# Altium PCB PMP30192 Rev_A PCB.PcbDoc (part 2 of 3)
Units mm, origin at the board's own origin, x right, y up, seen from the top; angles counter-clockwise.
Board outline 142.24 x 157.48 mm, 4 copper layers (Top Layer, Signal Layer 1, Signal Layer 2, Bottom Layer), stack 1.647 mm thick; 198 components, 99 nets, 479 pads, 192 vias.
Unrouted connection lines stored in the file: 2.
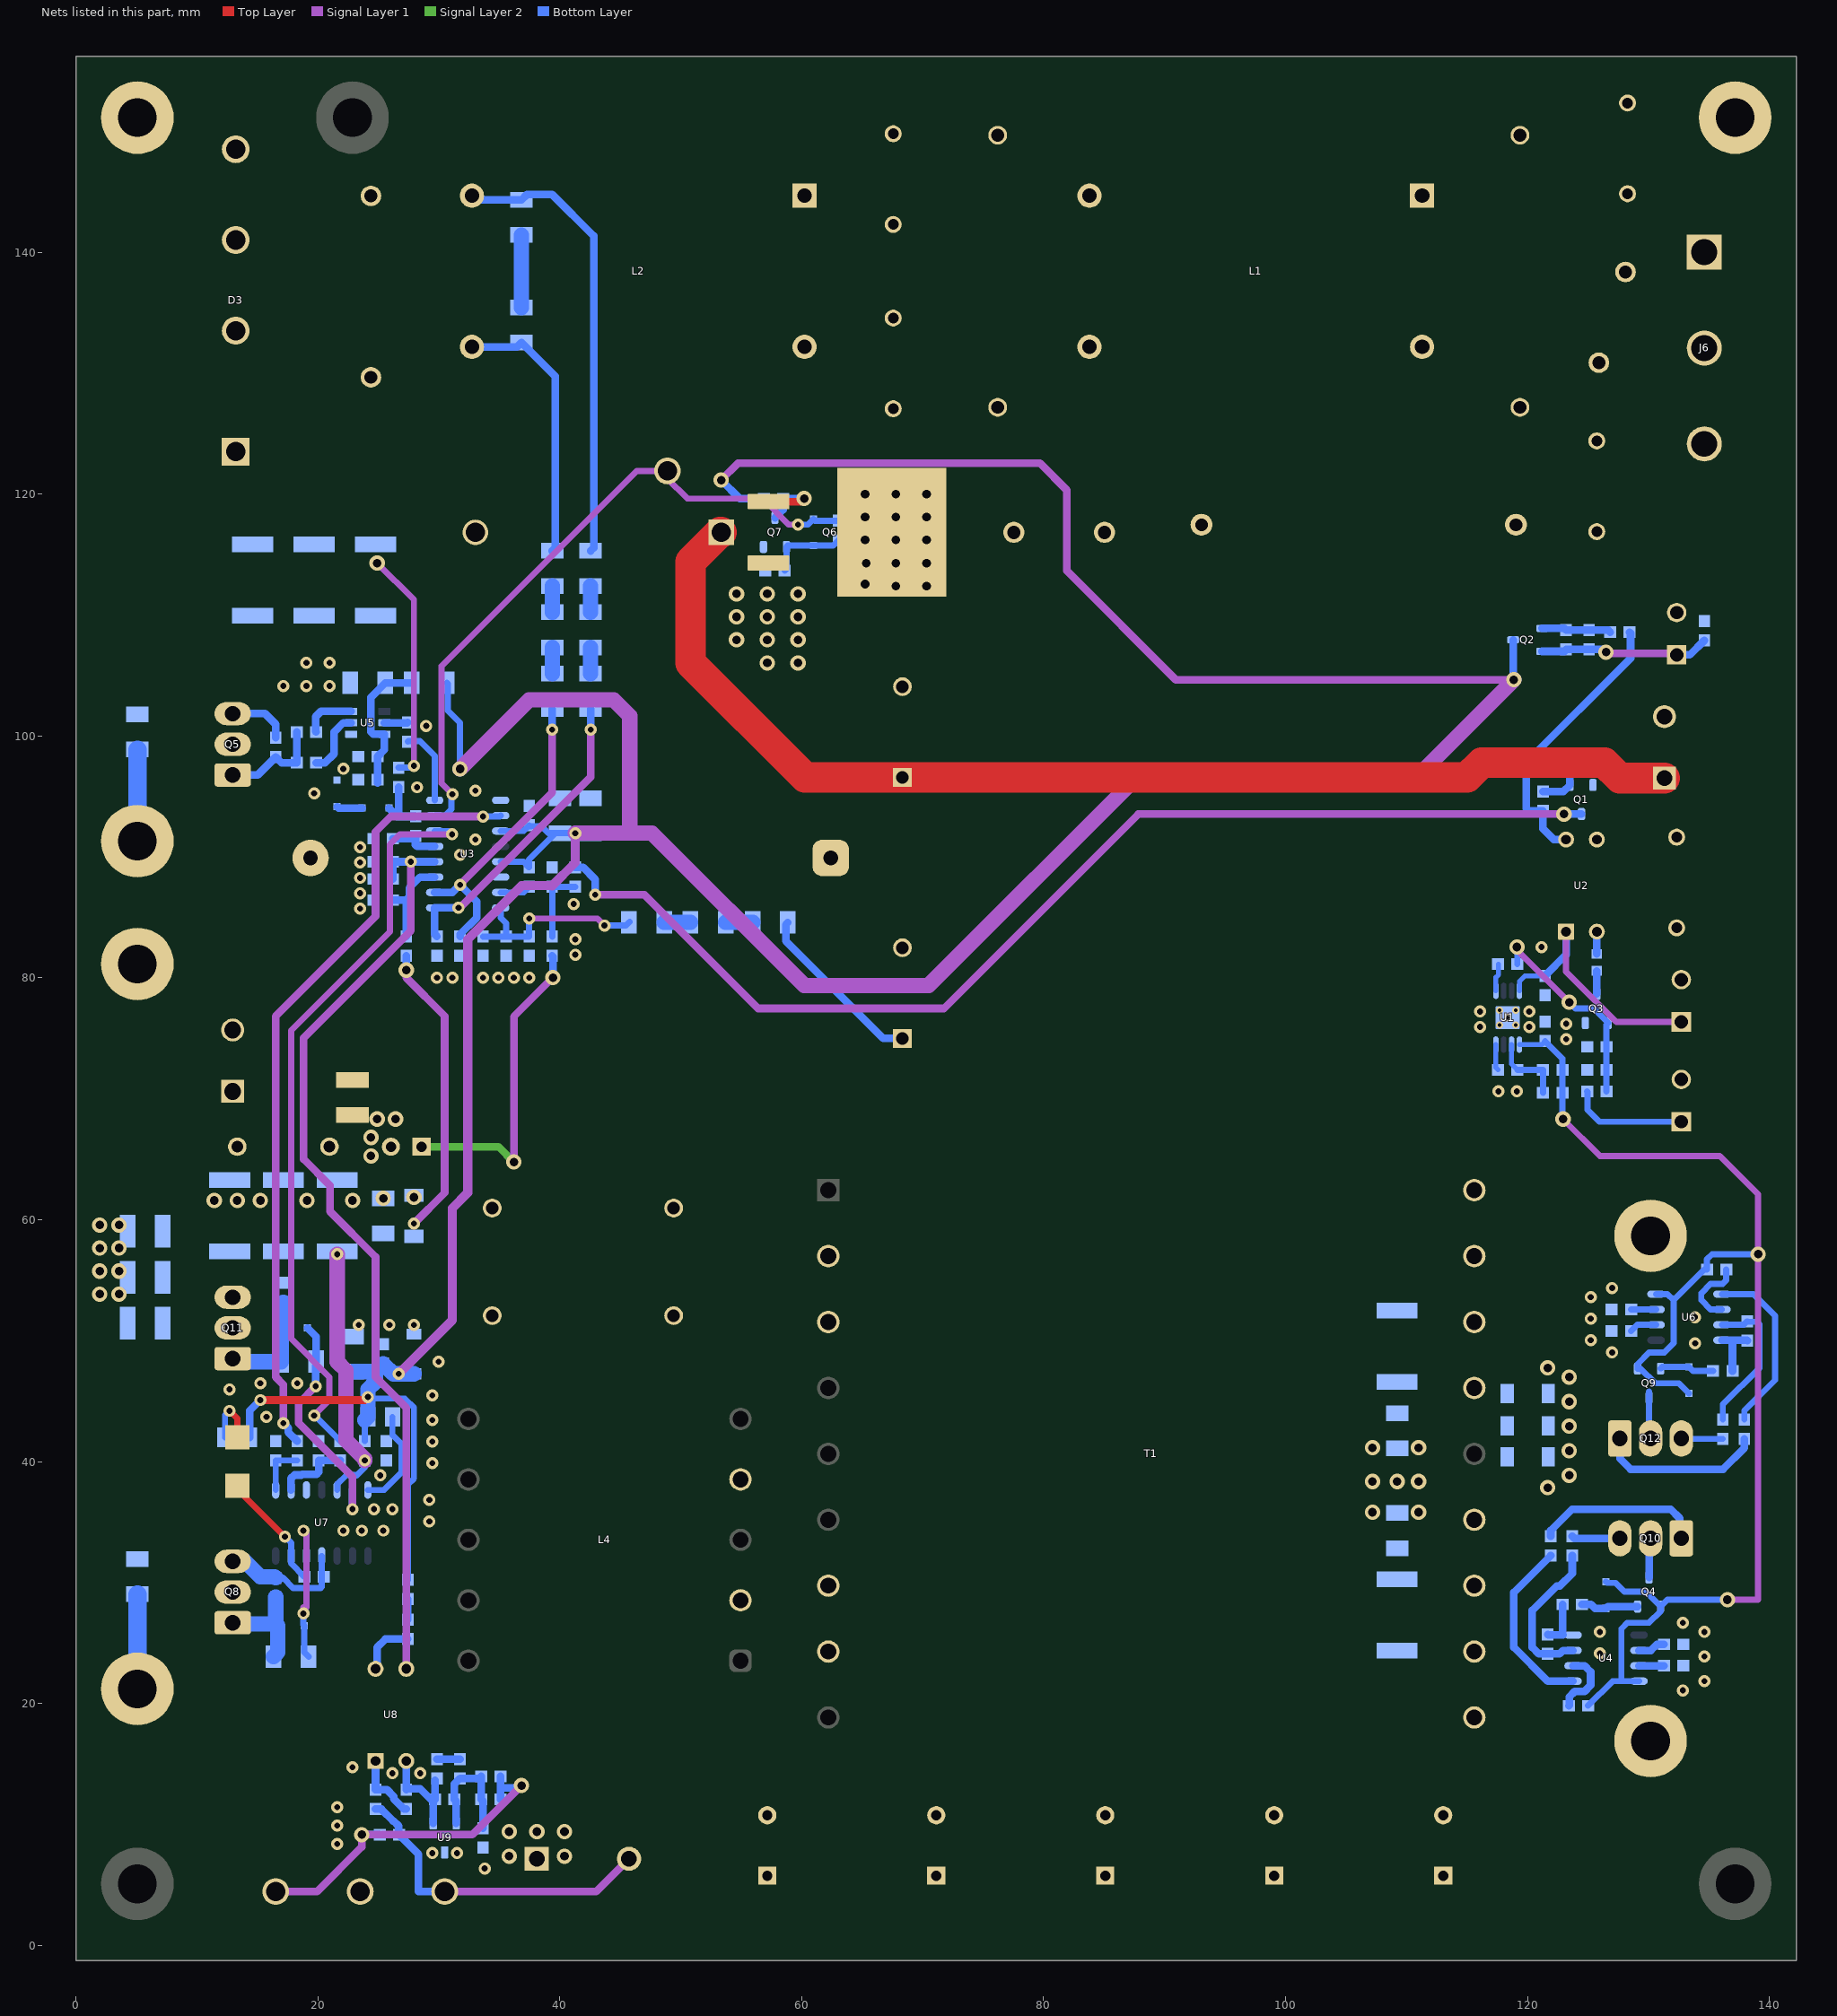
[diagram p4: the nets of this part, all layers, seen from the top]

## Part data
C1: "CAP, CERM, 4.7 µF, 10 V, +/- 20%, X5R, 0603"
C2 C27 C40 C41 C45: "CAP, CERM, 1 µF, 50 V, +/- 10%, X7R, 0603"
C3 C5 C8: "CAP, CERM, 0.01 µF, 100 V, +/- 5%, X7R, 0603"
C4 C6 C7 C16 C33 C43 C60: "CAP, CERM, 0.1uF, 50V, +/-10%, X7R, 0603"
C9 C10 C32 C59: "CAP, CERM, 10uF, 35V, +/-10%, X7R, 1206"
C11 C62: "CAP, CERM, 100 pF, 25 V, +/- 10%, X7R, 0603"
C12 C13 C14: "CAP, CERM, 470pF, 50V, +/-10%, X7R, 0603"
C15: "CAP, CERM, 1000pF, 50V, +/-10%, X7R, 0603"
C17 C63: "CAP, CERM, 2200 pF, 50 V, +/- 10%, X7R, 0603"
C18 C23: library part DE6B3KJ221KN3A, "CAP CER 100PF 300VAC 10% RADIAL"
C19 C26: "CAP, CERM, 220 pF, 300 V, +/- 10%, B, TH, 2- Leads, Body 8x7mm, Pin Spacing 7.5mm"
C20 C38: "CAP, CERM, 1 µF, 10 V, +/- 10%, X5R, 0603"
C21 C22: "CAP, Film, 0.47uF, 275V, +/-20%, TH"
C24: "CAP, Film, 0.33uF, 275V, +/-20%, TH"
C25 C39: "CAP, CERM, 47 pF, 50 V, +/- 5%, C0G/NP0, 0603"
C28 C29: library part 400KXW220MEFC18X45, "CAP, AL, 150 µF, 450 V, +/- 20%, TH"
C30 C31 C34: "CAP, CERM, 10 µF, 50 V, +/- 10%, X5R, 1206"
C35: "CAP, CERM, 2200 pF, 300 V, +/- 20%, E, TH, 2- Leads, Body 9x7mm, Pin Spacing 7.5mm"
C42 C58: library part Capacitor, "CAP, CERM, xxxF, xxV, [TempCo], xx%, [PackageReference]"
C44a C44b C44c C65: "CAP, CERM, 0.047 µF, 630 V, +/- 10%, X7R, 1210"
C46 C47 C48 C49 C50: library part 63ZLH470M12.5X25, "CAP, AL, 470 µF, 50 V, +/- 20%, 0.027 ohm, TH"
C52 C54: "CAP, CERM, 100pF, 50V, +/-1%, C0G/NP0, 0603"
C53: library part 121MPE223J, "CAP, Film, 0.018 µF, 1250 V, +/- 5%, TH"
C55: library part 121MPE223J, "CAP, Film, 0.015 µF, 1250 V, +/- 5%, TH"
C56: "CAP, CERM, 22 µF, 10 V, +/- 20%, X6S, 1206"
C57: "CAP, CERM, 47 µF, 16 V, +/- 15%, X5R, 1206"
C61: "CAP, CERM, 220 pF, 50 V, +/- 5%, C0G/NP0, 0603"
C64 C67: "CAP, CERM, 1000 pF, 630 V, +/- 10%, X7R, 1206"
D1 D2: "Diode, Ultrafast, 100V, 0.25A, SOD-323"
D3: library part GBJ3502-BP, "Diode, P-N-Bridge, 600 V, 15 A, TH"
D4: "Diode, Switching-Bridge, 600V, 3A, TH"
D5 D7 D8: "Diode, Ultrafast, 100 V, 0.25 A, SOD-323"
D6: "Diode, Schottky, 600V, 4A, TH"
D9 D11: library part BAS316,115, "Diode, Ultrafast, 100V, 0.25A, SOD-323"
D10: "Diode, Ultrafast, 600 V, 1 A, SMA"
D12: "Diode, Zener, 18V, 500mW, SOD-123"
F1: "Fuse, 8A, 250V, TH"
Fx1 Fx2 Fx3 TP2: library part PAD_100mil-40milhole, "100mil pad, 40mil hole"
HS1-Pin1 HS1-Pin2 HS3-Pin1 HS3-Pin2 HS4-ML26AAG-1 HS4-ML26AAG-2 TP7: "Test Point, Multipurpose, White, TH"
J1: "Terminal Block, 5.08 mm, 2x1, TH"
J2 J3 J5: "Terminal Block, 3.5 mm, 2x1, Tin, TH"
J4: "Header, 100mil, 2x1, TH"
J6: "Header, 312mil, 3x1, Tin, TH"
J7: "Jumper Wire, 300mil spacing, Orange, pkg of 200"
J8: "Terminal Block, 2x1, 7.62mm, TH"
L1: library part 744834405, "Coupled inductor, 1 mH, 10 A, 12.5mohm, TH"
L2: library part 744834405, "Coupled inductor, 3.3 mH, 5 A, 2 x 37mOhm, TH"
L3: "Inductor, Toroid, 470 µH, 0.11 ohm, TH"
L4: "Inductor, 54 µH, 0.0372 ohm, TH"
Q1 Q3: "MOSFET, N-CH, 60 V, 0.17 A, SOT-23"
Q2: library part "MMBT4403, Fairchild Semiconductor", "Transistor, PNP, 40 V, 0.6 A, SOT-23"
Q4 Q9: "MOSFET, N-CH, 100 V, 0.17 A, SOT-23"
Q5 Q8 Q11: library part IPP60R199CP, "MOSFET, N-CH, 600 V, 45 A, TO-220AB"
Q6: library part STB23NM50N, "MOSFET N CH 650V 35A D2PAK"
Q7: "MOSFET, N-CH, 50 V, 0.22 A, SOT-23"
Q10 Q12: library part "IPP023NE7N3 G", "MOSFET, N-CH, 100 V, 69 A, TO-220AB"
R1: "RES, 100, 1%, 0.1 W, 0603"
R2 R6 R21 R42: "RES, 100 k, 1%, 0.1 W, 0603"
R3 R10 R11 R15: "RES, 10.0 k, 1%, 0.1 W, 0603"
R4: "RES, 768 k, 1%, 0.1 W, 0603"
R5: "RES, 237 k, 1%, 0.1 W, 0603"
R7 R8 R9 R12 R13 R14: "RES, 3.09Meg ohm, 1%, 0.25W, 1206"
R16: "RES, 1.00 k, 1%, 0.1 W, 0603"
R17 R18 R19: "RES, 10.0Meg ohm, 1%, 0.25W, 1206"
R20: "RES, 1.0 k, 5%, 0.1 W, 0603"
R22: "RES, 75.0k ohm, 1%, 0.1W, 0603"
R23: "RES, 3.3Meg ohm, 5%, 0.1W, 0603"
R24 R25: "RES, 470 ohm, 1%, 0.1W, 0603"
R26: "RES, 2.21 k, 1%, 0.1 W, 0603"
R27: "RES, 3.32k ohm, 1%, 0.1W, 0603"
R28 R31: "RES, 475 k, 1%, 0.25 W, 1206"
R29: "RES, 3.3, 5%, 0.1 W, 0603"
R30 R36 R44 R49: "RES, 10.0, 1%, 0.1 W, 0603"
R32 R45: "RES, 100k ohm, 1%, 0.1W, 0603"
R33 R46: "RES, 221k ohm, 1%, 0.1W, 0603"
R34: "RES, 10, 5%, 0.1 W, 0603"
R35: "RES, 1.00, 1%, 0.1 W, 0603"
R37: "RES, 0, 5%, 0.25 W, 1206"
R38 R50 R58 R67 R70: "RES, 10.0k ohm, 1%, 0.1W, 0603"
R39 R40 R41: "RES, 0.08, 1%, 3 W, 2512"
R43: "RES, 221 k, 1%, 0.1 W, 0603"
R47 R56: "RES, 3.30 ohm, 1%, 0.25W, 1206"
R48: "RES, 2.2, 5%, 0.125 W, 0805"
R51: "RES, 1.00 ohm, 1%, 0.125W, 0805"
R52 R62: "DNP"
R53 R55: "RES, 51.1, 1%, 0.1 W, 0603"
R54 R57 R65: "RES, 0, 5%, 0.1 W, 0603"
R59 R60 R61: "RES, 1.00, 1%, 1 W, 2512"
R63: "RES, 20.0 k, 1%, 0.1 W, 0603"
R64: "RES, 49.9, 1%, 0.1 W, 0603"
R66: "RES, 1.21 k, 1%, 0.1 W, 0603"
R68: "RES, 107 k, 1%, 0.1 W, 0603"
R69: "RES, 19.6 k, 1%, 0.1 W, 0603"
RT1: library part B57237S229M, "Thermistor NTC, 22 ohm, 20%, 15x7mm"
RV1: "Varistor, 430V, 4.5KA, TH"
T1: "Transformer, 280 uH, TH"
TP1 TP5: "Test Point, Multipurpose, Red, TH"
TP6: "Test Point, Multipurpose, Black, TH"
U1: "Single Output LDO, 50 mA, Adjustable 1.175 to 26 V Output, 7 to 28 V Input, 8-pin MSOP (DGN), -40 to 125 degC, Green (RoHS & no Sb/Br)"
U2 U8: library part LTV-817, "Opto-Isolator, 1 Channel, TH"
U3: "CCM PFC and LLC Combo Controller, D0016A"
U4 U6: "GREEN Rectifier Controller Device, D0008A"
U5: "2.5-A and 5-A, 35-VMAX VDD FET and IGBT Single-Gate Driver, DBV0006A"
U7: "High-Speed,4A, 600V High-side Low-side Gate Driver Device, D0014A (SOIC-14)"
U9: "Adjustable Precision Shunt Regulator, 34 ppm / degC, 100 mA, -40 to 85 degC, 3-pin SOT-23 (DBZ), Green (RoHS & no Sb/Br)"

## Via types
v1: diameter 1, hole 0.5, Top Layer to Bottom Layer, 106 vias
v2: diameter 1.27, hole 0.711, Top Layer to Bottom Layer, 81 vias
v3: diameter 0.6, hole 0.3, Top Layer to Bottom Layer, 5 vias

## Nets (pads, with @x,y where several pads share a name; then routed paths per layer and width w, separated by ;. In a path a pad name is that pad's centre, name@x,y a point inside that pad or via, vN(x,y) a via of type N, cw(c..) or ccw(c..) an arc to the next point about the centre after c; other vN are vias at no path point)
5VS: C1.1 C5.2 C20.1 C38.1 D5.1 D7.1 Q4.1 Q9.1 R4.2 U1.1 U4.4 U6.4 | length 112.2
  Signal Layer 1 w0.508: v2(122.936,68.326) 125.984,65.278 135.89,65.278 139.065,62.103 v2(139.065,57.15) 139.065,28.575 v2(136.525,28.575)
  Bottom Layer w0.406: U1.1@119.331,74.483 121.168,74.483 C1.1@121.45,74.765
  Bottom Layer w0.508: C1.1@121.45,74.765 122.885,73.33 R4.2@122.885,72.39 C5.2@122.885,70.485 122.885,68.377 v2(122.936,68.326) ; C20.1@125.006,19.812 127.038,21.844 127.762,21.844 ; D5.1@126.492,30.056 126.576,29.972 127.267,29.972 128.004,29.235 129.773,29.235 Q4.1@130.998,28.01 ; U4.4@129.217,21.844 127.762,21.844 ; U6.4@130.625,53.848 131.572,53.848 132.08,53.34 ; D7.1@133.35,45.636 132.504,46.482 130.548,46.482 129.348,47.682 Q9.1@129.098,47.682 129.098,48.072 130.048,49.022 131.318,49.022 132.08,49.784 132.08,53.34 ; v2(136.525,28.575) 131.563,28.575 Q4.1@130.998,28.01 ; v2(139.065,57.15) 135.255,57.15 134.836,56.731 C38.1@134.836,55.88 134.62,55.88 132.08,53.34 ; 127.762,21.844 127.762,26.162 128.27,26.67 130.048,26.67 130.998,27.62 Q4.1@130.998,28.01
5VS_ENA: R11.1 U1.5 | length 2.3
  Bottom Layer w0.406: U1.5@117.381,78.933 117.381,80.043 117.602,80.264 R11.1@117.602,81.107
7VS: C4.1 J2.1 U1.8 U2.1 | length 22
  Signal Layer 1 w0.508: U2.1@123.19,83.82 123.19,80.518 127.353,76.355 J2.1@132.715,76.355
  Bottom Layer w0.406: U1.8@119.331,78.933 119.331,79.707 119.799,80.175 C4.1@121.45,80.175
  Bottom Layer w0.635: C4.1@121.45,80.175 123.19,81.915 U2.1@123.19,83.82
12V: C7.1 C9.2 C10.2 C41.2 C59.2 C60.1 D12.1 Q2.3 R6.1 R37.1 R42.2 R48.1 R51.2 R65.1 U3.3 U3.5 | length 321.9
  Top Layer w0.635: v1(15.24,45.085) 23.876,45.085 v1(24.13,45.339)
  Signal Layer 1 w0.635: v2(53.34,121.158) 54.737,122.555 79.7,122.555 81.915,120.34 81.915,113.665 90.932,104.648 v2(118.872,104.648)
  Signal Layer 1 w0.762: v1(26.67,47.258) 31.115,51.703 31.115,60.96 32.385,62.23 32.385,83.185 36.83,87.63 39.36,87.63 39.37,87.62 41.275,89.525 v1(41.275,91.962)
  Signal Layer 1 w1.27: v2(31.75,97.282) 37.465,102.997 44.45,102.997 45.783,101.663 45.783,92.026 45.72,91.962 ; v1(41.275,91.962) 45.72,91.962 ; v2(118.872,104.648) 111.379,97.155 88.265,97.155 70.485,79.375 60.212,79.375 47.625,91.962 45.72,91.962
  Bottom Layer w0.508: C41.2@23.876,41.694 R51.2@23.876,43.434 ; 24.13,44.704 24.638,45.212 27.178,45.212 27.94,44.45 27.94,38.608 27.432,38.1 R65.1@27.432,30.222 ; R37.1@30.66,104.394 30.734,104.32 30.734,102.108 31.75,101.092 v2(31.75,97.282) ; U3.5@35.11,89.602 36.995,89.602 R6.1@37.465,89.132 37.465,89.79 C9.2@39.638,91.962 ; U3.3@35.11,92.142 36.995,92.142 C7.1@37.465,92.612 37.554,92.523 38.481,92.523 39.042,91.962 C9.2@39.638,91.962 ; C10.2@42.545,91.962 v1(41.275,91.962) C9.2@40.005,91.962 C9.2@39.638,91.962
  Bottom Layer w0.635: R48.1@14.351,42.005 14.351,44.196 v1(15.24,45.085) ; v2(53.34,121.158) 54.864,119.634 R42.2@56.858,119.634 ; Q2.3@118.815,107.95 118.815,104.705 v2(118.872,104.648)
  Bottom Layer w1.27: C59.2@22.86,47.445 24.75,47.445 ; R51.2@23.876,43.434 R51.2@24.13,43.688 24.13,44.704 v1(24.13,45.339) 24.13,45.974 24.75,46.594 24.75,47.445 ; D12.1@27.94,47.258 v1(26.67,47.258) 26.237,47.258 C60.1@25.4,48.095 24.75,47.445
29V: C30.1 C31.1 C34.1 C46.1 C47.1 C48.1 C49.1 C50.1 J8.2 R63.2 R64.2 T1.12 T1.13 T1.15 T1.16 TP5.1 | length 27.1
  Signal Layer 1 w0.635: TP5.1@30.48,4.445 43.01,4.445 J8.2@45.72,7.155
  Bottom Layer w0.635: R63.2@24.765,11.265 25.273,11.265 25.273,11.226 26.212,10.287 26.252,10.287 26.67,9.869 26.67,9.182 R64.2@26.708,9.144 28.321,7.531 28.321,4.445 TP5.1@30.48,4.445
AC1: D3.2 L2.3 R12.2 R28.2 | length 23.1
  Bottom Layer w0.635: L2.3@33.02,131.892 L2.3@32.732,132.18 36.475,132.18 R28.2@36.83,132.535 39.624,129.741 39.624,115.563 R12.2@39.37,115.309
AC2: D3.3 L2.2 R7.2 R31.1 | length 38
  Bottom Layer w0.635: L2.2@32.732,144.68 33.087,144.325 R31.1@36.83,144.325 37.285,144.78 39.37,144.78 42.799,141.351 42.799,115.563 R7.2@42.545,115.309
AC_DET: D8.1 R43.1 TP1.1 U3.15 | length 55.8
  Signal Layer 1 w0.508: v1(31.115,95.187) 30.226,96.076 30.226,105.791 46.355,121.92 TP1.1@48.895,121.92 48.895,121.285 50.546,119.634 56.783,119.634 58.942,117.475 v1(59.69,117.475)
  Bottom Layer w0.508: U3.15@29.66,93.412 30.53,93.412 31.048,93.93 31.048,95.12 v1(31.115,95.187) ; v1(59.69,117.475) 60.495,117.475 D8.1@60.96,117.94 61.103,117.797 R43.1@63.05,117.797
BULK: C28.1 C29.1 C65.2 D4.1 D6.1 J1.1 J7.2 R17.1 | length 112
  Top Layer w2.54: D4.1@53.34,116.84 53.249,116.84 50.8,114.391 50.8,106.045 60.265,96.58 C28.1@68.326,96.58 114.995,96.58 116.205,97.79 126.365,97.79 127.635,96.52 J1.1@131.318,96.52
  Bottom Layer w0.635: R17.1@58.854,84.582 58.674,84.402 58.674,83.058 66.742,74.99 C29.1@68.326,74.99
FB: C17.1 R27.1 U3.12 U8.3 | length 78.8
  Signal Layer 1 w0.635: U8.3@27.305,22.86 27.305,44.45 24.765,46.99 24.765,56.92 20.993,60.691 20.993,62.827 18.82,65 18.82,75.044 27.686,83.91 v1(27.686,89.602)
  Bottom Layer w0.635: R27.1@26.2,88.172 C17.1@26.2,89.602 v1(27.686,89.602) U3.12@29.66,89.602
GD1: R55.2 U3.14 | length 62.5
  Signal Layer 1 w0.508: v1(19.685,43.815) 20.955,45.085 20.955,46.99 17.78,50.165 17.78,75.651 25.949,83.82 25.949,91.033 26.782,91.865 v1(31.098,91.865)
  Bottom Layer w0.508: v1(19.685,43.815) 19.723,43.815 R55.2@21.844,41.694 ; U3.14@29.66,92.142 30.82,92.142 v1(31.098,91.865)
GD2: R53.2 U3.2 | length 65.4
  Signal Layer 1 w0.508: 25.999,93.309 26.035,93.345
  Signal Layer 1 w0.635: v1(17.145,43.18) 17.145,46.355 16.51,46.99 16.51,76.835 24.765,85.09 24.765,92.075 25.999,93.309 ; 26.035,93.345 v1(33.655,93.345)
  Bottom Layer w0.508: v1(33.655,93.345) 35.043,93.345 U3.2@35.11,93.412
  Bottom Layer w0.635: v1(17.145,43.18) 17.145,43.177 17.557,42.766 17.557,42.425 R53.2@18.288,41.694
GND: C18.2 C19.2 C23.1 C26.1 J6.2 TP2.1
HIGH_POWER: J5.1 R20.1 | length 9.7
  Bottom Layer w0.508: R20.1@124.93,70.612 124.968,70.574 124.968,69.088 125.956,68.1 J5.1@132.715,68.1
LLC_RCS: C41.1 C44a.1 C44b.1 C44c.1 C53.2 C55.2 C56.1 C57.1 Q11.3 R26.1 R58.2 R59.2 R60.2 R61.2 U7.5 | length 46.5
  Signal Layer 1 w0.635: v2(27.305,80.645) 27.305,80.01 30.48,76.835 30.48,62.23 v1(27.94,59.69)
  Signal Layer 1 w1.27: v1(21.59,57.15) 21.59,48.26 22.319,47.531 22.319,41.769 23.876,40.212 v1(23.876,40.094)
  Bottom Layer w0.508: U7.5@21.59,37.65 21.59,38.1 22.373,38.883 23.195,38.883 23.216,38.862 23.876,39.522 v1(23.876,40.094) C41.1@23.838,40.056
  Bottom Layer w0.635: v2(27.305,80.645) R26.1@27.305,81.817
LP_ON: R3.1 R15.1 U2.4 | length 23.4
  Bottom Layer w0.635: U2.4@123.19,91.44 122.174,91.44 121.285,92.329 R3.1@121.285,93.815 120.053,93.815 119.888,93.98 119.888,97.79 128.524,106.426 128.524,108.496 R15.1@128.435,108.585
MD_SEL: C2.2 R1.2 R2.2 R6.2 U3.7 | length 10.5
  Bottom Layer w0.508: U3.7@35.11,87.062 36.995,87.062 R6.2@37.465,87.532 C2.2@39.37,87.532 ; R2.2@39.37,83.417 C2.2@39.37,87.532 ; R1.2@41.275,87.532 C2.2@39.37,87.532
NetC3_2: C3.2 Q1.1 R3.2 | length 4.5
  Bottom Layer w0.635: R3.2@121.285,95.415 122.975,95.415 Q1.1@123.51,95.95 123.51,97.775 C3.2@123.66,97.925
NetC5_1: C5.1 R4.1 R5.2 U1.2 | length 6.3
  Bottom Layer w0.406: U1.2@118.681,74.483 118.681,72.873 R5.2@119.164,72.39
  Bottom Layer w0.508: R5.2@119.164,72.39 R4.1@121.285,72.39 C5.1@121.285,70.485
NetC6_1: C6.1 C8.1 J3.1 Q2.2 R10.1 | length 14.2
  Signal Layer 1 w0.635: v2(126.492,106.934) 126.591,106.835 J3.1@132.395,106.835
  Bottom Layer w0.635: Q2.2@121.215,107 123.04,107 C8.1@123.19,107.15 R10.1@125.095,107.15 126.276,107.15 v2(126.492,106.934) ; J3.1@132.334,106.708 133.416,106.708 C6.1@134.62,107.912
NetC8_2: C8.2 Q2.1 R10.2 R15.2 | length 5.8
  Bottom Layer w0.635: Q2.1@121.215,108.9 123.04,108.9 C8.2@123.19,108.75 R10.2@125.095,108.75 126.67,108.75 R15.2@126.835,108.585
NetC11_1: C11.1 Q3.1 R11.2 R20.2 R21.2 | length 17.4
  Signal Layer 1 w0.508: v2(119.126,82.55) 119.126,82.296 v2(123.444,77.978)
  Bottom Layer w0.508: R11.2@119.156,81.153 v2@119.156,82.52 ; v2(123.444,77.978) 123.952,77.47 125.48,77.47 Q3.1@126.68,76.27 126.53,76.12 C11.1@126.53,74.295 R21.2@126.53,72.39 R20.2@126.53,70.612
NetC12_1: C12.1 R19.2 R22.1 R23.2 U3.8 | length 16.5
  Signal Layer 1 w0.508: v1(37.465,84.903) 43.113,84.903 v1(43.688,84.328)
  Bottom Layer w0.508: C12.1@33.655,83.417 R23.2@35.56,83.417 ; U3.8@35.11,85.792 35.11,84.972 35.56,84.522 R23.2@35.56,83.417 ; v1(37.465,84.903) R22.1@37.465,83.417 R23.2@35.56,83.417 ; v1(43.688,84.328) 45.47,84.328 R19.2@45.777,84.635
NetC13_1: C13.1 R14.1 U3.10 | length 25.5
  Signal Layer 1 w0.635: v1(31.75,87.697) 39.37,95.317 v1(39.37,100.524)
  Bottom Layer w0.635: U3.10@29.66,87.062 31.115,87.062 v1(31.75,87.697) 33.147,86.3 33.147,84.987 31.75,83.59 C13.1@31.75,83.417 ; v1(39.37,100.524) R14.1@39.37,102.249
NetC14_1: C14.1 R9.1 U3.9 | length 25.5
  Signal Layer 1 w0.635: v1(31.623,85.792) 31.75,85.792 42.545,96.587 v1(42.545,100.524)
  Bottom Layer w0.635: C14.1@29.845,83.417 29.66,83.602 U3.9@29.66,85.792 v1(31.623,85.792) ; v1(42.545,100.524) R9.1@42.545,102.249
NetC15_2: C15.2 R25.2 U3.13 | length 4.1
  Bottom Layer w0.635: C15.2@26.2,91.507 R25.2@27.851,91.507 ; R25.2@28.092,91.749 28.067,91.723 28.067,90.999 28.193,90.872 U3.13@29.66,90.872
NetC16_1: C16.1 R26.2 U3.11 | length 7.7
  Bottom Layer w0.635: C16.1@26.2,86.427 27.305,86.427 ; R26.2@27.305,83.417 27.305,86.427 ; U3.11@29.66,88.332 28.448,88.332 27.559,87.443 27.559,86.681 27.305,86.427
NetC18_1: C18.1 C21.1 J6.1 L1.4 RV1.2
NetC19_1: C19.1 C22.1 L1.3 L2.4
NetC21_2: C21.2 F1.1 L1.1 RV1.1
NetC22_2: C22.2 C26.2 L1.2 L2.1
NetC23_2: C23.2 F1.2 J6.3
NetC24_1: C24.1 D3.1 D4.2 L3.1
NetC25_1: C25.1 R36.1 U4.7 | length 12.8
  Bottom Layer w0.635: R36.1@123.698,32.22 123.698,30.734 122.682,29.718 122.428,29.718 120.396,27.686 120.396,24.638 120.942,24.092 C25.1@121.666,24.092 122.644,24.092 122.936,24.384 U4.7@123.767,24.384
NetC25_2: C25.2 R30.2 U4.8 | length 3.8
  Bottom Layer w0.635: C25.2@121.666,25.692 121.704,25.654 122.936,25.654 122.898,25.692 R30.2@122.898,28.194
NetC27_2: C27.2 C32.2 C33.1 R37.2 U5.3 | length 12.2
  Bottom Layer w0.635: C27.2@24.938,96.101 C27.2@24.938,96.393 C33.1@24.938,98.298 25.505,98.865 U5.3@25.505,100.142 24.572,100.142 24.384,100.33 24.384,103.198 C32.2@25.58,104.394 R37.2@27.76,104.394
NetC28_2: C28.2 C29.2 Q6.4 RT1.2
  other v2: 67.778,112.395 70.318,112.395 65.238,112.565 65.333,114.3 67.778,114.3 70.318,114.3 65.238,116.205 67.778,116.205 70.318,116.205 65.238,118.11 67.778,118.11 70.318,118.11 65.238,120.015 67.778,120.015 70.318,120.015
NetC39_1: C39.1 R49.1 U6.7 | length 12.5
  Bottom Layer w0.508: U6.7@136.075,51.308 137.884,51.308 C39.1@138.176,51.6 138.214,51.562 138.938,51.562 139.192,51.308 139.192,47.752 136.144,44.704 R49.1@136.144,43.472
NetC39_2: C39.2 R44.2 U6.8 | length 4.6
  Bottom Layer w0.635: U6.8@136.075,50.038 136.838,50.038 136.944,49.932 ; R44.2@136.944,47.498 136.944,49.932 ; C39.2@138.176,50 138.138,50.038 137.05,50.038 136.944,49.932
NetC40_2: C40.2 D8.2 Q7.1 R43.2 | length 6.6
  Bottom Layer w0.508: C40.2@58.585,113.665 58.735,113.815 Q7.1@58.735,115.64 58.835,115.74 D8.2@60.96,115.74 62.593,115.74 R43.2@63.05,116.197
NetC42_2: C42.2 R52.2
NetC43_1: C43.1 D10.1 U7.13 | length 9.8
  Top Layer w0.508: D10.1@13.335,38.005 13.335,37.719 v1(17.272,33.782)
  Bottom Layer w0.508: v1(17.272,33.782) 17.78,33.274 U7.13@17.78,32.2 17.78,31.585 C43.1@18.885,30.48
NetC43_2: C43.2 Q8.3 Q11.2 R50.1 T1.2 T1.3 U7.11 | length 10.9
  Bottom Layer w0.508: R50.1@16.51,30.391 17.107,30.391 17.947,29.551 20.233,29.551 20.32,29.638 U7.11@20.32,32.2
  Bottom Layer w1.27: Q8.3@12.954,31.75 13.97,31.75 15.24,30.48 16.421,30.48 R50.1@16.51,30.391
NetC44a_2: C44a.2 C44b.2 C44c.2 J7.1 Q8.2
  other v2: 1.956,53.848 3.556,53.848 1.956,55.753 3.556,55.753 1.956,57.655 3.556,57.658 1.956,59.56 3.556,59.56
NetC45_2: C45.2 R51.1 U7.7 | length 8.3
  Bottom Layer w0.508: U7.7@24.13,37.65 25.458,37.65 26.924,39.116 26.924,41.44 26.162,42.202 R51.1@26.162,43.688
NetC52_1: C52.1 R55.1 U7.2 | length 6.2
  Bottom Layer w0.635: U7.2@17.78,37.65 17.78,38.608 18.065,38.893 18.635,38.893 18.689,38.947 19.897,38.947 20.066,39.116 C52.1@20.066,40.094 R55.1@21.844,40.094
NetC53_1: C53.1 C55.1 L4.4
NetC54_2: C54.2 R53.1 U7.1 | length 4.2
  Bottom Layer w0.508: U7.1@16.51,37.65 C54.2@16.51,40.094 R53.1@18.288,40.094
NetC58_2: C58.2 R62.2
NetC61_1: C61.1 R64.1 R68.2 TP7.1 | length 30
  Signal Layer 1 w0.635: TP7.1@16.51,4.445 19.939,4.445 23.622,8.128 v2(23.622,9.144) 32.766,9.144 v2(36.83,13.208)
  Bottom Layer w0.635: v2(23.622,9.144) R64.1@25.108,9.144 ; C61.1@35.09,12.065 35.09,13.018 ; R68.2@35.09,13.97 35.09,13.018 ; v2(36.83,13.208) 36.83,12.954 36.766,13.018 35.09,13.018
NetC61_2: C61.2 C62.2 C63.2 R68.1 R70.2 U9.2 | length 10.1
  Bottom Layer w0.635: U9.2@31.43,10.09 31.43,11.915 C62.2@31.28,12.065 31.28,13.335 C63.2@31.75,13.805 33.325,13.805 R68.1@33.49,13.97 C61.2@33.49,12.065 33.655,11.9 R70.2@33.655,9.69
NetC62_1: C62.1 R67.1 R69.1 U8.2 U9.1 | length 8.8
  Bottom Layer w0.635: U8.2@27.305,15.24 R67.1@27.305,12.865 27.394,12.954 28.448,12.954 29.337,12.065 C62.1@29.68,12.065 ; U9.1@29.53,10.09 29.53,11.915 C62.1@29.68,12.065 ; R69.1@29.68,13.64 C62.1@29.68,12.065
NetC63_1: C63.1 R69.2 | length 1.9
  Bottom Layer w0.635: R69.2@29.845,15.405 C63.1@31.75,15.405
NetC64_1: C64.1 HS1-Pin1.1 HS1-Pin2.1 | length 7.6
  Bottom Layer w1.5: HS1-Pin2.1@5.08,91.313 C64.1@5.08,98.88
NetC67_1: C67.1 HS3-Pin1.1 HS3-Pin2.1 | length 7.8
  Bottom Layer w1.5: HS3-Pin1.1@5.08,21.209 C67.1@5.08,29.03
NetD1_1: D1.1 R24.2 R25.1 | length 5
  Bottom Layer w0.635: D1.1@25.865,94.047 26.564,93.349 ; R24.2@26.67,95.787 26.67,93.455 26.564,93.349 ; R25.1@28.092,93.349 26.564,93.349
NetD1_2: D1.2 D2.1 | length 2.1
  Bottom Layer w0.635: D2.1@21.59,94.15 21.693,94.047 D1.2@23.665,94.047
NetD5_2: D5.2 Q4.2 R30.1 | length 4.8
  Bottom Layer w0.635: R30.1@124.498,28.194 125.248,28.194 125.586,27.856 D5.2@126.492,27.856 126.646,28.01 Q4.2@129.098,28.01
NetD6_2: D6.2 L3.2 Q5.2
NetD7_2: D7.2 Q9.2 R44.1 | length 4.5
  Bottom Layer w0.508: Q9.2@130.998,47.698 131.136,47.836 D7.2@133.35,47.836 133.688,47.498 R44.1@135.344,47.498
NetD9_1: D9.1 R47.1 U7.12 | length 13.3
  Signal Layer 1 w0.508: v1(18.796,27.432) v1@18.796,27.686 ; 18.796,27.94 v1@18.796,27.686 ; v1(18.796,34.29) 19.05,34.036 19.05,27.94 v1@18.796,27.686
  Bottom Layer w0.508: v1(18.796,27.432) 18.796,26.5 D9.1@18.88,26.416 18.88,24.226 R47.1@19.23,23.876 ; v1(18.796,34.29) 19.05,34.036 U7.12@19.05,32.2
NetD9_2: D9.2 Q8.1 R47.2 R50.2 | length 8.5
  Bottom Layer w1.27: Q8.1@12.954,26.67 13.038,26.586 16.51,26.586 R50.2@16.51,28.791 ; R47.2@16.33,23.876 16.68,24.226 D9.2@16.68,26.416
NetD10_2: D10.2 R48.2 | length 4.8
  Top Layer w0.508: v1(12.7,44.196) 13.335,43.561 D10.2@13.335,42.005
  Bottom Layer w0.508: R48.2@12.319,42.005 12.319,43.815 v1(12.7,44.196)
NetD11_1: D11.1 R56.1 U7.6 | length 19.3
  Signal Layer 1 w0.635: v1(19.812,46.228) 18.415,44.831 18.415,43.18 22.86,38.735 v1(22.86,36.068)
  Bottom Layer w0.635: D11.1@19.134,51.054 19.865,50.323 R56.1@19.865,48.26 19.812,48.207 v1(19.812,46.228) ; v1(22.86,36.068) U7.6@22.86,37.65
NetD11_2: D11.2 Q11.1 R56.2 R58.1 | length 8.8
  Bottom Layer w1.27: Q11.1@13.208,48.26 R56.2@16.965,48.26 16.965,51.023 D11.2@16.934,51.054 16.934,52.964 R58.1@17.145,53.175
NetJ4_1: J4.1 R2.1 | length 26.6
  Signal Layer 1 w0.635: v2(36.195,64.77) 36.195,76.792 v2(39.427,80.024)
  Signal Layer 2 w0.635: J4.1@28.575,66.04 34.925,66.04 v2(36.195,64.77)
  Bottom Layer w0.635: R2.1@39.37,81.817 39.427,81.761 v2(39.427,80.024)
NetL4_2: L4.2 T1.7 T1.8
NetQ1_3: Q1.3 R1.1 | length 95.4
  Signal Layer 1 w0.635: v1(42.926,86.868) 46.99,86.868 56.388,77.47 71.755,77.47 87.825,93.54 v2(123.01,93.54)
  Bottom Layer w0.635: R1.1@41.275,89.132 41.932,89.132 42.926,88.138 v1(42.926,86.868) ; v2(123.01,93.54) 124.45,93.54 Q1.3@124.46,93.55
NetQ3_3: Q3.3 R16.1 | length 1.9
  Bottom Layer w0.635: Q3.3@125.73,78.67 R16.1@125.73,80.58
NetQ5_1: Q5.1 R29.2 R35.2 R38.1 | length 8.6
  Bottom Layer w0.635: Q5.1@12.954,96.774 15.024,96.774 R38.1@16.51,98.26 16.98,97.79 R35.2@18.25,97.79 R29.2@18.25,100.33
NetQ6_1: Q6.1 Q7.3 R42.1 | length 6.7
  Top Layer w0.635: Q6.1@57.25,119.38 59.944,119.38 v2(60.198,119.634)
  Bottom Layer w0.635: Q7.3@57.785,118.04 58.458,118.713 R42.1@58.458,119.634 v2(60.198,119.634)
NetQ10_1: Q10.1 R54.1 | length 13.9
  Bottom Layer w0.635: R54.1@121.92,33.82 121.92,34.29 123.698,36.068 131.826,36.068 132.588,35.306 132.588,33.782 Q10.1@132.715,33.655
NetQ12_1: Q12.1 R57.1 | length 13.8
  Bottom Layer w0.635: Q12.1@127.635,41.91 127.635,40.259 128.524,39.37 136.17,39.37 137.922,41.122 R57.1@137.922,41.872
NetR7_1: R7.1 R8.2 | length 2.2
  Bottom Layer w1.27: R8.2@42.545,110.229 R7.1@42.545,112.409
NetR8_1: R8.1 R9.2 | length 2.2
  Bottom Layer w1.27: R9.2@42.545,105.149 R8.1@42.545,107.329
NetR12_1: R12.1 R13.2 | length 2.2
  Bottom Layer w1.27: R13.2@39.37,110.229 R12.1@39.37,112.409
NetR13_1: R13.1 R14.2 | length 2.2
  Bottom Layer w1.27: R14.2@39.37,105.149 R13.1@39.37,107.329
NetR16_2: R16.2 U2.2 | length 1.8
  Bottom Layer w0.635: R16.2@125.73,81.98 U2.2@125.73,83.82
NetR17_2: R17.2 R18.1 | length 2.3
  Bottom Layer w1.27: R18.1@53.704,84.582 R17.2@55.954,84.582
NetR18_2: R18.2 R19.1 | length 2.2
  Bottom Layer w1.27: R19.1@48.624,84.582 R18.2@50.804,84.582
NetR28_1: R28.1 R31.2 | length 6
  Bottom Layer w1.27: R28.1@36.83,135.435 R31.2@36.83,141.425
NetR29_1: R29.1 U5.6 | length 4.4
  Bottom Layer w0.635: R29.1@19.85,100.33 19.812,100.368 19.812,101.6 20.254,102.042 U5.6@22.755,102.042
NetR32_2: R32.2 U4.3 | length 2.1
  Bottom Layer w0.635: U4.3@129.217,23.114 R32.2@131.28,23.114
NetR33_2: R33.2 U4.2 | length 2.3
  Bottom Layer w0.635: U4.2@129.217,24.384 130.192,24.384 130.7,24.892 R33.2@131.28,24.892
NetR34_1: R34.1 U5.2 | length 1.9
  Bottom Layer w0.635: U5.2@25.505,101.092 27.394,101.092 R34.1@27.432,101.13
NetR35_1: R35.1 U5.5 | length 5.3
  Bottom Layer w0.635: R35.1@19.85,97.79 20.6,97.79 21.336,98.526 21.336,100.33 22.098,101.092 U5.5@22.755,101.092
NetR45_2: R45.2 U6.3 | length 2.1
  Bottom Layer w0.508: R45.2@128.562,52.578 U6.3@130.625,52.578
NetR46_2: R46.2 U6.2 | length 2.3
  Bottom Layer w0.508: R46.2@128.562,50.8 129.07,51.308 U6.2@130.625,51.308
NetR63_1: R63.1 R67.2 U8.1 | length 5.7
  Bottom Layer w0.635: U8.1@24.765,15.24 R63.1@24.765,12.865 25.705,12.865 26.259,12.312 26.259,12.128 27.122,11.265 R67.2@27.305,11.265
NetR65_2: R65.2 R66.1 | length 1.7
  Bottom Layer w0.635: R66.1@27.432,26.92 R65.2@27.432,28.622
NetR66_2: R66.2 U8.4 | length 4.7
  Bottom Layer w0.635: U8.4@24.765,22.86 24.892,22.987 24.892,24.638 25.574,25.32 R66.2@27.432,25.32
PFCCS: C24.2 D3.4 R24.1 R39.2 R40.2 R41.2 | length 19.4
  Signal Layer 1 w0.508: v2(24.892,114.3) 27.94,111.252 v1(27.94,97.536)
  Bottom Layer w0.508: R24.1@26.67,97.387 27.791,97.387 v1(27.94,97.536)
PFCGD: R34.2 U3.16 | length 6.4
  Bottom Layer w0.508: R34.2@27.432,99.53 27.47,99.568 28.448,99.568 29.66,98.356 U3.16@29.66,94.682
PGND: C2.1 C3.1 C6.2 C7.2 C9.1 C10.1 C12.2 C13.2 C14.2 C15.1 C16.2 C17.2 C27.1 C32.1 C33.2 C35.2 C40.1 C45.1 C52.2 C54.1 C56.2 C57.2 C59.1 C60.2 C64.2 C65.1 C67.2 D2.2 D12.2 J1.2 J3.2 J4.2 Q1.2 Q5.3 Q6.3 Q7.2 R22.2 R23.1 R27.2 R38.2 R39.1 R40.1 R41.1 R59.1 R60.1 R61.1 RT1.1 U2.3 U3.1 U3.6 U5.4 U7.3 | length 5
  Bottom Layer w0.635: Q5.3@12.954,101.854 15.621,101.854 16.51,100.965 R38.2@16.51,99.86
  other v1: 22.098,34.29 23.622,34.29 25.4,34.29 29.21,35.052 24.638,36.068 26.162,36.068 29.21,36.83 25.146,38.862 29.464,39.878 29.464,41.656 29.464,43.434 15.748,43.688 29.464,45.466 12.7,45.974 15.24,46.482 18.288,46.482 29.972,48.26 23.368,51.308 25.908,51.308 27.94,51.308 29.845,80.01 31.115,80.01 33.655,80.01 34.925,80.01 36.195,80.01 37.465,80.01 41.275,81.915 41.275,83.185 23.495,85.725 41.148,86.106 23.495,86.995 23.495,88.265 23.495,89.535 31.75,90.17 23.495,90.805 33.02,91.44 19.685,95.25 33.02,95.487 28.194,95.758 22.098,97.282 28.956,100.838 17.145,104.14 19.05,104.14 20.955,104.14 19.05,106.045 20.955,106.045
  other v2: 11.43,61.595 13.335,61.595 15.24,61.595 19.095,61.595 22.86,61.595 25.4,61.775 27.94,61.85 24.384,65.278 24.384,66.802 24.892,68.326 26.416,68.326 57.15,106.045 59.69,106.045 54.61,107.95 57.15,107.95 59.69,107.95 54.61,109.855 57.15,109.855 59.69,109.855 54.61,111.76 57.15,111.76 59.69,111.76
SGND: C1.2 C4.2 C11.2 C20.2 C30.2 C31.2 C34.2 C35.1 C38.2 C42.1 C46.2 C47.2 C48.2 C49.2 C50.2 C58.1 J2.2 J5.2 J8.1 Q3.2 Q10.3 Q12.3 R5.1 R21.1 R32.1 R33.1 R36.2 R45.1 R46.1 R49.2 R70.1 TP6.1 U1.4 U1.9 U4.6 U6.6 U9.3 | length 21.3
  Bottom Layer w0.406: U1.4@117.381,74.483 117.381,72.573 R5.1@117.564,72.39
  Bottom Layer w0.508: Q12.3@132.715,41.91 132.753,41.872 R49.2@136.144,41.872 ; U6.6@136.075,52.578 135.128,52.578 134.366,53.34 134.366,53.931 135.128,54.693 136.144,54.693 136.436,54.985 C38.2@136.436,55.88
  Bottom Layer w0.635: C20.2@123.406,19.812 123.444,19.85 123.444,20.537 123.906,20.999 124.714,20.999 125.222,21.507 125.222,22.606 124.714,23.114 U4.6@123.767,23.114 ; R36.2@123.698,33.82 123.863,33.655 Q10.3@127.635,33.655
  other v1: 33.782,6.35 29.464,7.62 31.496,7.62 21.59,8.382 21.59,9.906 21.59,11.43 26.162,14.224 28.448,14.224 22.86,14.732 132.842,21.082 134.62,21.844 134.62,23.876 125.984,24.13 125.984,25.908 134.62,25.908 132.842,26.67 127,49.022 133.858,49.784 125.222,50.038 125.222,51.816 133.85,51.943 125.222,53.594 127,54.356 117.602,70.612 119.126,70.612 123.19,74.93 116.078,75.946 120.142,75.946 123.19,76.2 116.078,77.216 120.142,77.216 121.158,82.55
  other v2: 35.814,7.366 40.386,7.366 35.814,9.398 38.1,9.398 40.386,9.398 107.188,35.814 110.998,35.814 121.666,37.846 107.188,38.354 109.22,38.354 110.998,38.354 123.444,38.862 123.444,40.894 107.188,41.148 110.998,41.148 123.444,42.926 123.444,44.958 123.444,46.99 121.666,47.752
  other v3: 117.704,76.098 119.024,76.098 118.356,76.708 117.704,77.318 119.024,77.318
VD_SR1: HS4-ML26AAG-2.1 Q9.3 Q12.2 R62.1 T1.17 T1.18 | length 3.9
  Bottom Layer w0.508: 130.048,45.79 130.048,42.037 Q12.2@130.175,41.91
VD_SR2: HS4-ML26AAG-1.1 Q4.3 Q10.2 R52.1 T1.10 T1.11 | length 3.3
  Bottom Layer w0.635: Q4.3@130.048,30.41 130.048,33.528 Q10.2@130.175,33.655
VG_SR1: R57.2 U6.5 | length 14.8
  Bottom Layer w0.508: U6.5@136.075,53.848 138.684,53.848 140.462,52.07 140.462,46.736 137.922,44.196 R57.2@137.922,43.472
VG_SR2: R54.2 U4.5 | length 14.9
  Bottom Layer w0.635: R54.2@121.92,32.22 118.872,29.172 118.872,24.638 121.666,21.844 U4.5@123.767,21.844
pads on no net: Fx1.1 Fx2.1 Fx3.1 L4.1 L4.3 L4.5 L4.6 L4.7 L4.8 L4.9 L4.10 T1.1 T1.4 T1.5 T1.6 T1.9 T1.14 U1.3 U1.6 U1.7 U3.4 U4.1 U5.1 U6.1 U7.4 U7.8 U7.9 U7.10 U7.14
